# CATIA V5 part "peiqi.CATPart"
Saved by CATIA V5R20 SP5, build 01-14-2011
Part number: 小猪佩奇
Material "Kingwood": density 700 kg/m3, Young's modulus 1.3e+10 Pa
Material "Bright Orange": density 7860 kg/m3, Young's modulus 2e+11 Pa, Poisson ratio 0.266
Bounding box of the stored display mesh (mm): x -250 to 250, y -150 to 240, z -60 to 120
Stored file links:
  E:\180222129\peiqi.CATPart
  C:\Program Files\Dassault Systemes\B20\intel_a\startup\materials\Catalog.CATMaterial
  C:\Program Files\Dassault Systemes\B20\intel_a\startup\materials\dirty_wall.jpg
  C:\Program Files\Dassault Systemes\B20\intel_a\startup\materials\eroded_metal_1.jpg
  C:\Program Files\Dassault Systemes\B20\intel_a\startup\materials\kingwood.jpg
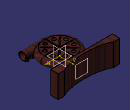
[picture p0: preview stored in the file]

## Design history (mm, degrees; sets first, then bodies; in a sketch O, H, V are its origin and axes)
Body1 (main body), material "Kingwood"
  Sketch1 on xy-plane, origin (0, 0, 0), H (1, 0, 0), V (0, 1, 0)
    circle A1 centre (0, 0) radius 150
    radius A1 = 150
  Pad1: profile Sketch1, direction (0, 0, 1), length 30
  Fillet1: radius 30, on edge [start face of Pad1 | face of Pad1 from Sketch1.A1]
  Shell1: ExtOffset 0, Face end face of Pad1, IntOffset 2
  Mirror1: of the body so far, about end face of Pad1
  Sketch2 on yz-plane, origin (0, 0, 0), H (0, 1, 0), V (0, 0, 1)
    circle A1 centre (-120, 30) radius 30
    point P1 (-120, 30)
    reference projected line E1 (-120, 0) -> (120, 0) from edge [start face of Pad1 | face of Fillet1]
    radius A1 = 30
    distance P1 V = 120
    distance P1 E1 = 30
  Pad2: profile Sketch2, direction (1, 0, 0), length 180
  Sketch3 on end face of Pad2, origin (180, -120, 30), H (0, 1, 0), V (0, 0, 1)
    point P1 (0, 0)
  Hole1: placed by Sketch3, at (180, -120, 30) direction (-1, 0, 0), diameter 58, depth 180
  Sketch4 on start face of Pad1, origin (0, 0, 0), H (1, 0, 0), V (0, -1, 0)
    circle A1 centre (0, 0) radius 75
    radius A1 = 75
  Sketch5 on start face of Pad1, origin (0, 0, 0), H (1, 0, 0), V (0, -1, 0)
    circle A1 centre (-83.1027, 60.8536) radius 20
    radius A1 = 20
  Pad3: profile Sketch4, direction (0, 0, -1), length 5
  Pad4: profile Sketch5, direction (0, 0, -1), length 5
  Sketch6 on start face of Pad1, origin (0, 0, 0), H (1, 0, 0), V (0, -1, 0)
    spline S1 through (-22.9309, -93.3616) (0, -97.7689) (18.8215, -93.3616) (76.2923, -57.1234)
    offsetcurve C1
    point P1 (-23.5537, -94.7261)
    point P2 (77.2558, -58.273)
  Line1: type PtPt, FirstPoint vertex of Sketch6, SecondPoint Sketch6.P2
  Line2: type PtPt, FirstPoint vertex of Sketch6, SecondPoint Sketch6.P1
  Join1: Elements (Line1; Sketch6; Line2)
  Pad5: profile Join1, length 5, mirrored extent
  Sketch7 on start face of Pad1, origin (0, 0, 0), H (1, 0, 0), V (0, -1, 0)
    line L1 (51.1552, 111.4277) -> (28.0611, 111.4277)
    line L2 (28.0611, 111.4277) -> (16.5141, 91.4277)
    line L3 (16.5141, 91.4277) -> (28.0611, 71.4277)
    line L4 (28.0611, 71.4277) -> (51.1552, 71.4277)
    line L5 (51.1552, 71.4277) -> (62.7022, 91.4277)
    line L6 (62.7022, 91.4277) -> (51.1552, 111.4277)
    construction line L7 (39.6082, 91.4277) -> (39.6082, 111.4277)
    line L8 (-24.0545, 98.0153) -> (-35.6015, 98.0153)
    line L9 (-35.6015, 98.0153) -> (-41.375, 88.0153)
    line L10 (-41.375, 88.0153) -> (-35.6015, 78.0153)
    line L11 (-35.6015, 78.0153) -> (-24.0545, 78.0153)
    line L12 (-24.0545, 78.0153) -> (-18.281, 88.0153)
    line L13 (-18.281, 88.0153) -> (-24.0545, 98.0153)
    construction line L14 (-29.828, 88.0153) -> (-29.828, 98.0153)
    circle A1 centre (39.6082, 91.4277) radius 10
    circle A2 centre (-29.828, 88.0153) radius 5
    distance L1 L4 = 40
    angle L7 H = 90
    distance L8 L11 = 20
    angle L14 H = 90
    radius A1 = 10
    radius A2 = 5
  Pad6: profile Sketch7, direction (0, 0, -1), length 20
  Sketch8 on start face of Pad1, origin (0, 0, 0), H (1, 0, 0), V (0, -1, 0)
    line L1 (108.682, 134.1923) -> (94.2482, 134.1923)
    line L2 (94.2482, 134.1923) -> (87.0313, 121.6923)
    line L3 (87.0313, 121.6923) -> (94.2482, 109.1923)
    line L4 (94.2482, 109.1923) -> (108.682, 109.1923)
    line L5 (108.682, 109.1923) -> (115.8989, 121.6923)
    line L6 (115.8989, 121.6923) -> (108.682, 134.1923)
    construction line L7 (101.4651, 121.6923) -> (101.4651, 134.1923)
    line L8 (151.4719, 134.1923) -> (137.0381, 134.1923)
    line L9 (137.0381, 134.1923) -> (129.8212, 121.6923)
    line L10 (129.8212, 121.6923) -> (137.0381, 109.1923)
    line L11 (137.0381, 109.1923) -> (151.4719, 109.1923)
    line L12 (151.4719, 109.1923) -> (158.6887, 121.6923)
    line L13 (158.6887, 121.6923) -> (151.4719, 134.1923)
    construction line L14 (144.255, 121.6923) -> (144.255, 134.1923)
    circle A1 centre (101.4651, 121.6923) radius 7
    circle A2 centre (144.255, 121.6923) radius 7
    distance L1 L4 = 25
    angle L7 H = 90
    distance L8 L11 = 25
    angle L14 H = 90
    radius A1 = 7
    radius A2 = 7
  Pad7: profile Sketch8, direction (0, 0, -1), length 20
  Sketch9 on face of Mirror1, origin (0, 0, 60), H (1, 0, 0), V (0, 1, 0)
    point P1 (-22.1434, 9.8541)
    ellipse A1 centre (-1.6853, -60.176) semi-axes 5, 52.4712 rotation 358.276
    ellipse A2 centre (60.176, -1.6853) semi-axes 5, 52.4712 rotation 88.276
    ellipse A3 centre (1.6853, 60.176) semi-axes 5, 52.4712 rotation 178.276
    ellipse A4 centre (-60.176, 1.6853) semi-axes 5, 52.4712 rotation 268.276
    ellipse A5 centre (-41.3592, 43.7425) semi-axes 5, 52.4712 rotation 223.276
    ellipse A6 centre (-43.7425, -41.3592) semi-axes 5, 52.4712 rotation 313.276
    ellipse A7 centre (41.3592, -43.7425) semi-axes 5, 52.4712 rotation 43.276
    ellipse A8 centre (43.7425, 41.3592) semi-axes 5, 52.4712 rotation 133.276
  Sketch10 on face of Mirror1, origin (0, 0, 60), H (1, 0, 0), V (0, 1, 0)
    circle A1 centre (84.0802, 32.1016) radius 15
    point P1 (84.0802, 32.1016)
    circle A2 centre (82.153, -36.7544) radius 15
    circle A3 centre (32.1016, -84.0802) radius 15
    circle A4 centre (-36.7544, -82.153) radius 15
    circle A5 centre (-82.153, 36.7544) radius 15
    circle A6 centre (-84.0802, -32.1016) radius 15
    circle A7 centre (-32.1016, 84.0802) radius 15
    circle A8 centre (36.7544, 82.153) radius 15
    radius A1 = 15
    distance P1 O = 90
  Pocket1: profile Sketch10, direction (0, 0, -1), length 20
  Pocket2: profile Sketch9, direction (0, 0, -1), length 20
  Sketch11 on xy-plane, origin (0, 0, 0), H (1, 0, 0), V (0, 1, 0)
    circle A1 centre (0, 0) radius 5
    point P1 (5, 0)
    radius A1 = 5
    coincidence: A1 P1, P1 H
  Pad8: profile Sketch11, direction (0, 0, 1), length 60
  Plane1: type Offset, RefPlane zx-plane, Offset 180
  Sketch12 on Plane1, origin (0, 180, 0), H (-1, 0, 0), V (0, 0, 1)
    point P1 (0, 30)
    line L1 (250, 120) -> (250, -60)
    line L2 (250, -60) -> (-250, -60)
    line L3 (-250, -60) -> (-250, 120)
    line L4 (-250, 120) -> (250, 120)
    length L1 = 180
    length L4 = 500
    coincidence: P1 V
    vertical: L1 V, L3 V
    horizontal: L2 H, L4 H
    equidistance: L1 L3 P1, L2 L4 P1
  Pad9: profile Sketch12, direction (0, 1, 0), length 60
  Sketch13 on face of Pad9 from Sketch12.L4, origin (0, 0, 120), H (1, 0, 0), V (0, 1, 0)
    ellipse A1 centre (0, 300) semi-axes 250, 100 rotation 0
    point P2 (0, 200)
    "Radius" A1 = 250
    coincidence: P2 V, A1 P2
  Pocket3: profile Sketch13, direction (0, 0, -1), length 180
  Sketch14 on xy-plane, origin (0, 0, 0), H (1, 0, 0), V (0, 1, 0)
    reference intersected line E1 through (0, 180) direction (-1, 0) from Plane1
    reference projected point E2 (0, 0) from edge
    distance E1 E2 = 180 (reference)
